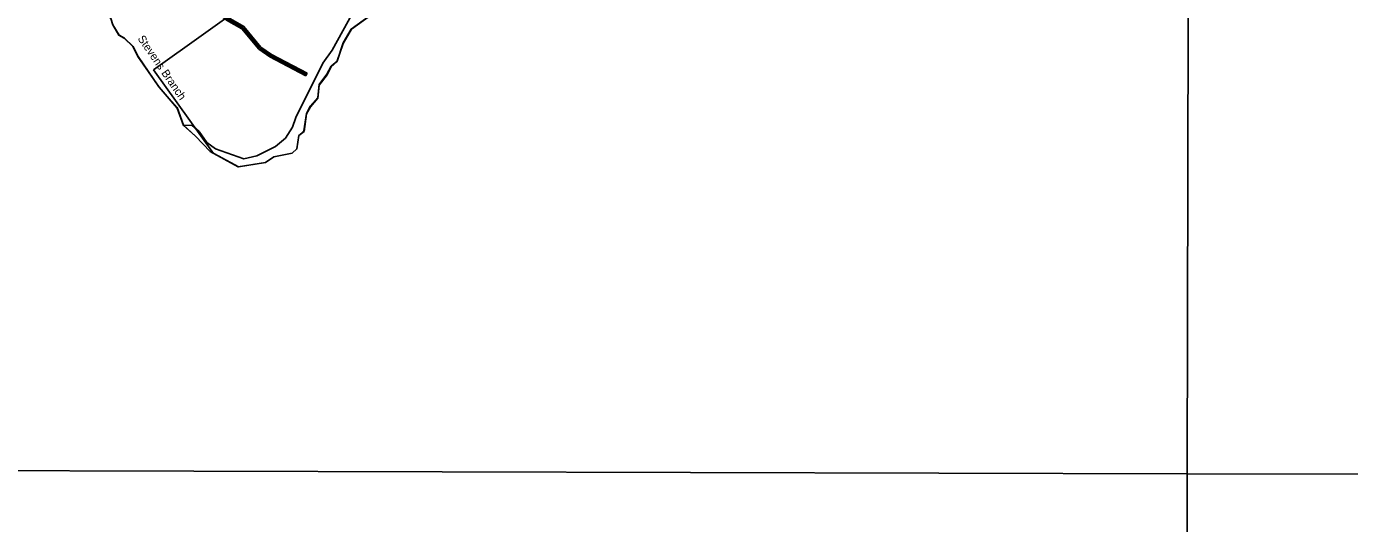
# Model space of a CAD drawing. Extents: x 418523 to 616617, y 1878279 to 2196743.
# Drawn here: x 553602 to 580050, y 1922740 to 1932665 of the extents above; entities that cross this region are included whole.
import ezdxf

# ---------------------------------------------------------------- set-up
doc = ezdxf.new("R2010")
doc.units = 0
for name, color, linetype in [('Level 1', 7, 'Continuous'), ('Level 10', 7, 'Continuous'), ('Level 31', 7, 'Continuous'), ('Level 32', 7, 'Continuous'), ('Level 41', 7, 'Continuous'), ('Level 5', 7, 'Continuous'), ('Level 63', 7, 'Continuous'), ('Level 7', 7, 'Continuous')]:
    doc.layers.add(name, color=color, linetype=linetype)

msp = doc.modelspace()

# ---------------------------------------------------------------- linework, layer by layer
at = {"layer": 'Level 1'}
for p, q in [((556141.631, 1931802.529), (559339.422, 1934081.568)), ((557340.121, 1930130.972), (556141.631, 1931802.529))]:
    msp.add_line(p, q, dxfattribs=at)
at = {"layer": 'Level 10'}
msp.add_lwpolyline([(560621.486, 1932992.72), (560095.481, 1932610.704), (559936.481, 1932335.695), (559810.483, 1931969.685), (559693.482, 1931869.681), (559609.483, 1931711.676), (559450.482, 1931503.669), (559425.486, 1931244.662), (559274.485, 1931070.656), (559199.486, 1930928.652), (559148.49, 1930579.643), (559048.489, 1930487.64), (559005.491, 1930220.632), (558913.491, 1930137.63), (558546.484, 1930063.623), (558379.482, 1929947.618), (557837.472, 1929865.609), (557271.456, 1930167.609), (556980.445, 1930476.612), (556739.437, 1930693.614), (556615.429, 1931044.621), (556249.416, 1931462.626), (555834.397, 1932063.635), (555734.392, 1932263.638), (555560.386, 1932430.64), (555452.383, 1932489.64), (555327.377, 1932698.643)], dxfattribs=at)
at = {"layer": 'Level 31'}
msp.add_lwpolyline([(559201.196, 1931704.241), (558485.213, 1932081.411), (558268.964, 1932232.17), (557928.244, 1932641.452), (557620.264, 1932817.186), (557337.536, 1933051.404), (557396.766, 1933343.256), (557597.636, 1933742.732), (558032.622, 1934266.683), (558025.316, 1934625.26), (557918.196, 1935075.741), (557859.995, 1935167.536), (557860.261, 1935267.538), (557902.116, 1935359.066), (557919.238, 1935467.388)], dxfattribs=at)
at = {"layer": 'Level 32'}
msp.add_line((559187.214, 1931677.697), (559215.178, 1931730.784), dxfattribs=at)
for points in [[(559187.214, 1931677.697), (558469.583, 1932055.736), (558248.491, 1932209.87), (557908.661, 1932618.086), (557603.132, 1932792.421), (557304.562, 1933039.763), (557368.161, 1933353.151), (557572.37, 1933759.265), (558002.4, 1934277.246), (557995.387, 1934621.441), (557890.171, 1935063.916), (557829.971, 1935158.863), (557830.277, 1935274.111), (557873.124, 1935367.807), (557882.558, 1935427.484)], [(559215.178, 1931730.784), (558500.843, 1932107.086), (558289.436, 1932254.47), (557947.827, 1932664.818), (557637.396, 1932841.952), (557370.511, 1933063.045), (557425.37, 1933333.36), (557622.903, 1933726.2), (558062.845, 1934256.119), (558055.245, 1934629.078), (557946.221, 1935087.566), (557890.018, 1935176.209), (557890.244, 1935260.966), (557931.106, 1935350.325), (557943.75, 1935430.301)]]:
    msp.add_lwpolyline(points, dxfattribs=at)
at = {"layer": 'Level 5'}
for points in [[(556741.517, 1930685.634), (556617.579, 1931036.151), (556252.126, 1931454.146), (555828.927, 1932064.075), (555729.552, 1932264.468), (555555.006, 1932431.75), (555446.833, 1932490.43), (555330.777, 1932699.233), (555289.485, 1932824.416), (555139.989, 1932991.628), (555065.456, 1933141.911), (554924.161, 1933275.751), (554665.894, 1933334.92)], [(557839.272, 1929865.139), (558381.422, 1929946.768), (558548.514, 1930062.923), (558915.541, 1930136.77), (559007.531, 1930219.842), (559050.059, 1930486.47), (559150.36, 1930569.513), (559201.486, 1930919.471), (559276.976, 1931060.966), (559427.586, 1931235.532), (559453.443, 1931493.899), (559612.483, 1931701.786), (559696.372, 1931859.911), (559805.073, 1931959.595), (559931.291, 1932325.995), (560098.901, 1932608.914), (560625.336, 1932990.68), (560692.705, 1933207.196)], [(557839.272, 1929865.139), (557273.376, 1930167.079), (556982.586, 1930476.432), (556741.517, 1930685.634)]]:
    msp.add_lwpolyline(points, dxfattribs=at)
at = {"layer": 'Level 63'}
for points in [[(537087.28, 1923840.983), (576804.214, 1923734.416), (576901.847, 1969190.287), (537233.897, 1969297.112), (537087.28, 1923840.983)], [(576804.213, 1923734.416), (616520.63, 1923670.374), (616569.073, 1969126.078), (576901.846, 1969190.287), (576804.213, 1923734.416)], [(536941.231, 1878385.707), (576706.958, 1878279.4), (576804.214, 1923734.416), (537087.28, 1923840.983), (536941.231, 1878385.707)]]:
    msp.add_lwpolyline(points, dxfattribs=at)
at = {"layer": 'Level 7'}
msp.add_lwpolyline([(556741.517, 1930685.634), (556908.281, 1930693.446), (557057.906, 1930567.906), (557207.271, 1930350.672), (557381.947, 1930225.071), (557948.162, 1930023.164), (558206.787, 1930080.709), (558582.512, 1930271.228), (558783.134, 1930437.305), (558917.204, 1930653.621), (558984.512, 1930845.167), (559529.878, 1931935.461), (559714.088, 1932193.299), (560351.405, 1933358.365)], dxfattribs=at)

# ---------------------------------------------------------------- texts
at = {"layer": 'Level 41'}
msp.add_text('Stevens Branch', height=160, rotation=304.6284139, dxfattribs=at).set_placement((555817.919, 1932421.529))

doc.saveas('drawing.dxf')
